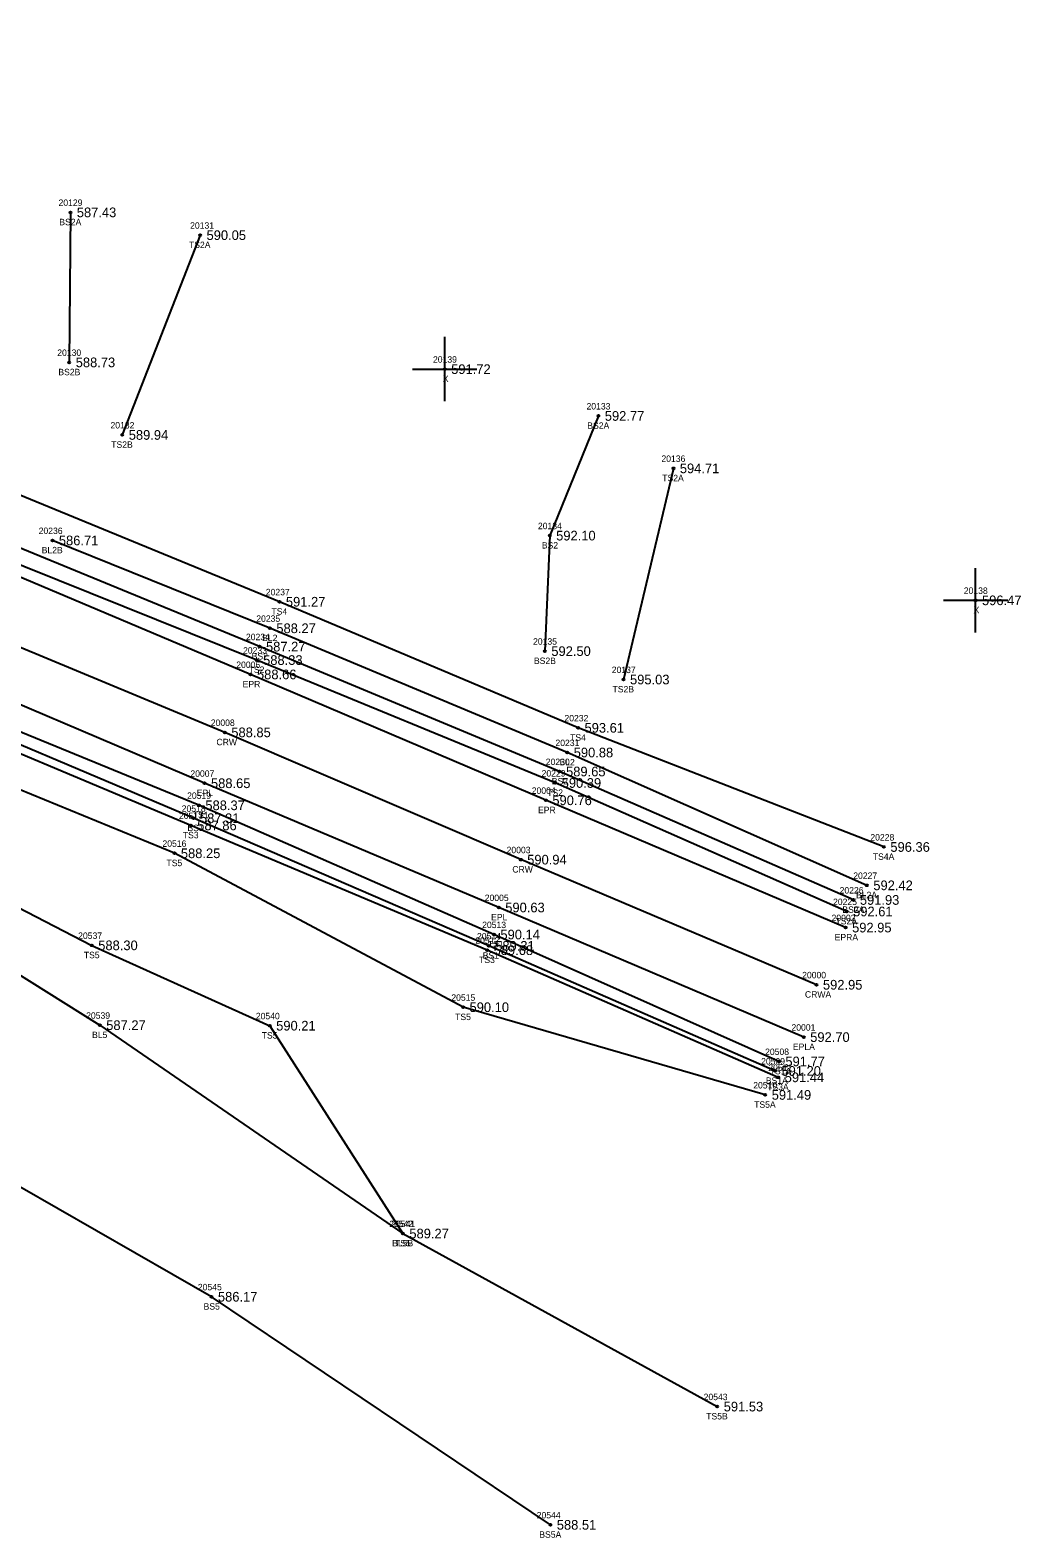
# Model space of a CAD drawing. Extents: x 1664837 to 1666270, y 987403 to 988245.
# Drawn here: x 1666036.4 to 1666190.4, y 987402.8 to 987637 of the extents above; entities that cross this region are included whole.
import ezdxf

# ---------------------------------------------------------------- set-up
doc = ezdxf.new("R2010")
doc.units = 0
for name, color, linetype in [('RD_DTM_BkLn1', 7, 'Continuous'), ('RD_DTM_BkLn2', 7, 'Continuous'), ('RD_DTM_BkLn_txCode', 7, 'Continuous'), ('RD_EX_Misc', 7, 'Continuous'), ('RD_EX_Misc_txCode', 7, 'Continuous'), ('RD_EX_Road', 7, 'Continuous'), ('RD_EX_Road_txCode', 7, 'Continuous'), ('RD_EX_TX_Misc_ELEV', 7, 'Continuous'), ('RD_EX_TX_Road_ELEV', 7, 'Continuous'), ('RD_HC_Survey_ELEV', 7, 'Continuous'), ('RD_HC_Survey_txCode', 7, 'Continuous'), ('RD_SMD_Locator', 7, 'Continuous')]:
    doc.layers.add(name, color=color, linetype=linetype)

msp = doc.modelspace()

# ---------------------------------------------------------------- linework, layer by layer
at = {"layer": 'RD_DTM_BkLn1'}
for points in [[(1666158.65, 987488.74), (1666112.69, 987508.17), (1666066.71, 987527.94), (1666020.54, 987547.08), (1665974.85, 987566.77), (1665928.96, 987586.52), (1665882.66, 987605.79), (1665836.76, 987625.38), (1665790.86, 987644.81), (1665744.75, 987663.93), (1665698.8, 987683.39), (1665652.93, 987702.82), (1665606.7, 987721.88), (1665561.04, 987742.04), (1665527.67, 987755.89)], [(1666166.48, 987504.18), (1666119.92, 987524.81), (1666073.71, 987544.11), (1666039.91, 987557.75)], [(1666003.31, 987510), (1666047.27, 987482.46), (1666094.38, 987450.1)]]:
    msp.add_lwpolyline(points, dxfattribs=at)
at = {"layer": 'RD_DTM_BkLn2'}
for p, q in [((1666042.7, 987608.71), (1666042.53, 987585.41)), ((1666062.86, 987605.17), (1666050.77, 987574.14)), ((1666136.41, 987568.95), (1666128.67, 987536.15))]:
    msp.add_line(p, q, dxfattribs=at)
for points in [[(1666152.82, 987476.83), (1666108.53, 987496.54), (1666062.68, 987516.61), (1666015.91, 987535.8), (1665969.55, 987555.16), (1665926.09, 987572.12), (1665875.73, 987592.3), (1665829.7, 987613.88), (1665783.86, 987631.56), (1665738.66, 987650.04), (1665693.22, 987670.26), (1665645.99, 987690.14), (1665601.24, 987708.82), (1665555.03, 987727.9), (1665522.94, 987740.22)], [(1666117.29, 987404.85), (1666064.63, 987440.28), (1666022.87, 987464.18), (1665976.62, 987505.49), (1665934.85, 987514.58), (1665901.43, 987514.29), (1665891.04, 987542.26), (1665910.76, 987561.83), (1665873.03, 987584.83), (1665826.13, 987605.22), (1665781.49, 987626.06), (1665735.29, 987642.75), (1665690.09, 987662.74), (1665646.61, 987681.64)], [(1666163.34, 987500.12), (1666118.05, 987520.08), (1666071.65, 987539.17), (1666025.11, 987557.83), (1665979.84, 987578.73), (1665950.61, 987593.05)], [(1666164.39, 987501.91), (1666118.73, 987521.86), (1666072.1, 987541.26), (1666025.93, 987560.23), (1665978.36, 987581.05), (1665950.61, 987593.05)], [(1666169.13, 987510.14), (1666121.6, 987528.65), (1666075.19, 987548.23), (1666028, 987567.6), (1665980.89, 987586.17)], [(1666152.2, 987475.35), (1666107.72, 987494.78), (1666061.84, 987514.6), (1666015.3, 987534.28), (1665968.59, 987553.61), (1665925.46, 987570.75), (1665883.85, 987585.11)], [(1666152.71, 987474.36), (1666107.47, 987494.11), (1666061.41, 987513.49), (1666014.8, 987533.07), (1665968.17, 987552.49), (1665925.11, 987569.65), (1665883.85, 987585.11)], [(1666124.75, 987577.09), (1666117.19, 987558.5), (1666116.44, 987540.56)], [(1666150.69, 987471.63), (1666103.73, 987485.25), (1666058.87, 987509.16), (1666012.36, 987528.21), (1665967.23, 987548.46), (1665923.96, 987565.08), (1665912.9, 987557.68), (1665922.58, 987537.56), (1665935.15, 987537.59), (1665963.45, 987533.43), (1666001.19, 987518.01), (1666046.03, 987494.86), (1666073.68, 987482.38), (1666094.38, 987450.1), (1666143.23, 987423.22)]]:
    msp.add_lwpolyline(points, dxfattribs=at)
at = {"layer": 'RD_EX_Misc'}
for p, q in [((1666100.88, 987579.36), (1666100.88, 987589.36)), ((1666095.88, 987584.36), (1666105.88, 987584.36)), ((1666183.37, 987543.45), (1666183.37, 987553.45)), ((1666178.37, 987548.45), (1666188.37, 987548.45))]:
    msp.add_line(p, q, dxfattribs=at)
at = {"layer": 'RD_EX_Road'}
for points in [[(1666163.18, 987497.62), (1666116.6, 987517.39), (1666070.7, 987536.94), (1666024.42, 987556.43), (1665979.02, 987575.67), (1665932.35, 987595.55), (1665886.93, 987614.54), (1665839.87, 987634.25), (1665794.5, 987653.27), (1665748.81, 987672.51), (1665702.36, 987691.87), (1665656.42, 987711.45), (1665610.33, 987731.03), (1665564.85, 987750.93), (1665531.47, 987764.82)], [(1666156.67, 987480.61), (1666109.28, 987500.74), (1666063.55, 987520.04), (1666017.04, 987539.82), (1665971.11, 987559.14), (1665924.88, 987578.79), (1665879.5, 987597.89), (1665833.22, 987617.38), (1665786.91, 987636.81), (1665741.44, 987656.13), (1665695.81, 987675.2), (1665649.26, 987694.85), (1665603.56, 987714.71), (1665558.4, 987733.87), (1665524.71, 987748.93)]]:
    msp.add_lwpolyline(points, dxfattribs=at)
at = {"layer": 'RD_SMD_Locator'}
for centre in [(1666042.7, 987608.71), (1666062.86, 987605.17), (1666042.53, 987585.41), (1666100.88, 987584.36), (1666124.75, 987577.09), (1666050.77, 987574.14), (1666136.41, 987568.95), (1666039.91, 987557.75), (1666117.19, 987558.5), (1666075.19, 987548.23), (1666183.37, 987548.45), (1666073.71, 987544.11), (1666072.1, 987541.26), (1666071.65, 987539.17), (1666116.44, 987540.56), (1666070.7, 987536.94), (1666128.67, 987536.15), (1666066.71, 987527.94), (1666121.6, 987528.65), (1666119.92, 987524.81), (1666063.55, 987520.04), (1666118.05, 987520.08), (1666118.73, 987521.86), (1666062.68, 987516.61), (1666116.6, 987517.39), (1666061.41, 987513.49), (1666061.84, 987514.6), (1666058.87, 987509.16), (1666169.13, 987510.14), (1666112.69, 987508.17), (1666166.48, 987504.18), (1666164.39, 987501.91), (1666109.28, 987500.74), (1666163.34, 987500.12), (1666163.18, 987497.62), (1666046.03, 987494.86), (1666107.72, 987494.78), (1666108.53, 987496.54), (1666107.47, 987494.11), (1666158.65, 987488.74), (1666103.73, 987485.25), (1666047.27, 987482.46), (1666073.68, 987482.38), (1666156.67, 987480.61), (1666152.82, 987476.83), (1666152.2, 987475.35), (1666152.71, 987474.36), (1666150.69, 987471.63), (1666094.38, 987450.1), (1666094.38, 987450.1), (1666064.63, 987440.28), (1666143.23, 987423.22), (1666117.29, 987404.85)]:
    msp.add_circle(centre, 0.15, dxfattribs=at)

# ---------------------------------------------------------------- texts
at = {"layer": 'RD_DTM_BkLn_txCode'}
for s, p in [('20129', (1666040.86, 987609.71)), ('BS2A', (1666040.98, 987606.71)), ('20131', (1666061.31, 987606.17)), ('TS2A', (1666061.13, 987603.17)), ('20130', (1666040.66, 987586.41)), ('BS2B', (1666040.83, 987583.41)), ('20133', (1666122.91, 987578.09)), ('20132', (1666048.93, 987575.14)), ('BS2A', (1666123.03, 987575.09)), ('TS2B', (1666049.05, 987572.14)), ('20136', (1666134.55, 987569.95)), ('TS2A', (1666134.68, 987566.95)), ('20134', (1666115.36, 987559.5)), ('20236', (1666037.77, 987558.75)), ('BL2B', (1666038.24, 987555.75)), ('BS2', (1666115.96, 987556.5)), ('20237', (1666073.07, 987549.23)), ('20235', (1666071.59, 987545.11)), ('TS4', (1666073.95, 987546.23)), ('20234', (1666069.98, 987542.26)), ('BL2', (1666072.5, 987542.11)), ('20135', (1666114.6, 987541.56)), ('20233', (1666069.53, 987540.17)), ('BS2', (1666070.87, 987539.26)), ('BS2B', (1666114.74, 987538.56)), ('TS2', (1666070.4, 987537.17)), ('20137', (1666126.83, 987537.15)), ('TS2B', (1666126.95, 987534.15)), ('20232', (1666119.48, 987529.65)), ('TS4', (1666120.36, 987526.65)), ('20231', (1666118.08, 987525.81)), ('20230', (1666116.58, 987522.86)), ('BL2', (1666118.71, 987522.81)), ('20229', (1666115.93, 987521.08)), ('BS2', (1666117.51, 987519.86)), ('20519', (1666060.84, 987517.61)), ('TS2', (1666116.8, 987518.08)), ('20517', (1666059.57, 987514.49)), ('20518', (1666060, 987515.6)), ('TS1', (1666061.72, 987514.61)), ('BS1', (1666060.89, 987512.6)), ('20516', (1666057.01, 987510.16)), ('TS3', (1666060.17, 987511.49)), ('20228', (1666167.02, 987511.14)), ('TS4A', (1666167.4, 987508.14)), ('TS5', (1666057.63, 987507.16)), ('20227', (1666164.36, 987505.18)), ('20226', (1666162.24, 987502.91)), ('20225', (1666161.22, 987501.12)), ('BL2A', (1666164.79, 987502.18)), ('TS2A', (1666161.61, 987498.12)), ('BS2A', (1666162.67, 987499.91)), ('20537', (1666043.91, 987495.86)), ('20514', (1666105.89, 987495.78)), ('20513', (1666106.69, 987497.54)), ('20512', (1666105.63, 987495.11)), ('TS1', (1666107.57, 987494.54)), ('TS5', (1666044.79, 987492.86)), ('TS3', (1666106.22, 987492.11)), ('BS1', (1666106.78, 987492.78)), ('20515', (1666101.9, 987486.25)), ('20539', (1666045.15, 987483.46)), ('20540', (1666071.52, 987483.38)), ('TS5', (1666102.49, 987483.25)), ('BL5', (1666046.07, 987480.46)), ('TS5', (1666072.43, 987480.38)), ('20508', (1666150.66, 987477.83)), ('20509', (1666150.04, 987476.35)), ('20511', (1666151.16, 987475.36)), ('TS1A', (1666151.37, 987474.83)), ('20510', (1666148.82, 987472.63)), ('BS1A', (1666150.77, 987473.35)), ('TS3A', (1666150.98, 987472.36)), ('TS5A', (1666148.96, 987469.63)), ('20542', (1666092.26, 987451.1)), ('20541', (1666092.55, 987451.1)), ('BL5B', (1666092.7, 987448.1)), ('TS5', (1666093.14, 987448.1)), ('20545', (1666062.51, 987441.28)), ('BS5', (1666063.4, 987438.28)), ('20543', (1666141.11, 987424.22)), ('TS5B', (1666141.51, 987421.22)), ('20544', (1666115.17, 987405.85)), ('BS5A', (1666115.57, 987402.85))]:
    msp.add_text(s, height=1, dxfattribs=at).set_placement(p)
at = {"layer": 'RD_EX_Misc_txCode'}
for s, p in [('20139', (1666099.05, 987585.36)), ('X', (1666100.57, 987582.36)), ('20138', (1666181.54, 987549.45)), ('X', (1666183.06, 987546.45))]:
    msp.add_text(s, height=1, dxfattribs=at).set_placement(p)
at = {"layer": 'RD_EX_Road_txCode'}
for s, p in [('20006', (1666068.48, 987537.94)), ('EPR', (1666069.47, 987534.94)), ('20007', (1666061.35, 987521.04)), ('EPL', (1666062.34, 987518.04)), ('20004', (1666114.4, 987518.39)), ('EPR', (1666115.37, 987515.39)), ('20005', (1666107.09, 987501.74)), ('EPL', (1666108.08, 987498.74)), ('20002', (1666160.99, 987498.62)), ('EPRA', (1666161.47, 987495.62)), ('20001', (1666154.76, 987481.61)), ('EPLA', (1666154.98, 987478.61))]:
    msp.add_text(s, height=1, dxfattribs=at).set_placement(p)
at = {"layer": 'RD_EX_TX_Misc_ELEV'}
for s, p in [('587.43', (1666043.7, 987607.96)), ('590.05', (1666063.86, 987604.42)), ('588.73', (1666043.53, 987584.66)), ('591.72', (1666101.88, 987583.61)), ('592.77', (1666125.75, 987576.34)), ('589.94', (1666051.77, 987573.39)), ('594.71', (1666137.41, 987568.2)), ('586.71', (1666040.91, 987557)), ('592.10', (1666118.19, 987557.75)), ('591.27', (1666076.19, 987547.48)), ('596.47', (1666184.37, 987547.7)), ('588.27', (1666074.71, 987543.36)), ('587.27', (1666073.1, 987540.51)), ('592.50', (1666117.44, 987539.81)), ('588.33', (1666072.65, 987538.42)), ('595.03', (1666129.67, 987535.4)), ('593.61', (1666122.6, 987527.9)), ('590.88', (1666120.92, 987524.06)), ('589.65', (1666119.73, 987521.11)), ('590.39', (1666119.05, 987519.33)), ('588.37', (1666063.68, 987515.86)), ('587.86', (1666062.41, 987512.74)), ('587.31', (1666062.84, 987513.85)), ('596.36', (1666170.13, 987509.39)), ('588.25', (1666059.87, 987508.41)), ('592.42', (1666167.48, 987503.43)), ('591.93', (1666165.39, 987501.16)), ('592.61', (1666164.34, 987499.37)), ('590.14', (1666109.53, 987495.79)), ('588.30', (1666047.03, 987494.11)), ('589.68', (1666108.47, 987493.36)), ('589.31', (1666108.72, 987494.03)), ('590.10', (1666104.73, 987484.5)), ('587.27', (1666048.27, 987481.71)), ('590.21', (1666074.68, 987481.63)), ('591.20', (1666153.2, 987474.6)), ('591.77', (1666153.82, 987476.08)), ('591.44', (1666153.71, 987473.61)), ('591.49', (1666151.69, 987470.88)), ('589.27', (1666095.38, 987449.35)), ('589.27', (1666095.38, 987449.35)), ('586.17', (1666065.63, 987439.53)), ('591.53', (1666144.23, 987422.47)), ('588.51', (1666118.29, 987404.1))]:
    msp.add_text(s, height=1.5, dxfattribs=at).set_placement(p)
at = {"layer": 'RD_EX_TX_Road_ELEV'}
for s, p in [('588.66', (1666071.7, 987536.19)), ('588.65', (1666064.55, 987519.29)), ('590.76', (1666117.6, 987516.64)), ('590.63', (1666110.28, 987499.99)), ('592.95', (1666164.18, 987496.87)), ('592.70', (1666157.67, 987479.86))]:
    msp.add_text(s, height=1.5, dxfattribs=at).set_placement(p)
at = {"layer": 'RD_HC_Survey_ELEV'}
for s, p in [('588.85', (1666067.71, 987527.19)), ('590.94', (1666113.69, 987507.42)), ('592.95', (1666159.65, 987487.99))]:
    msp.add_text(s, height=1.5, dxfattribs=at).set_placement(p)
at = {"layer": 'RD_HC_Survey_txCode'}
for s, p in [('20008', (1666064.52, 987528.94)), ('CRW', (1666065.4, 987525.94)), ('20003', (1666110.49, 987509.17)), ('CRW', (1666111.38, 987506.17)), ('20000', (1666156.42, 987489.74)), ('CRWA', (1666156.85, 987486.74))]:
    msp.add_text(s, height=1, dxfattribs=at).set_placement(p)

doc.saveas('drawing.dxf')
